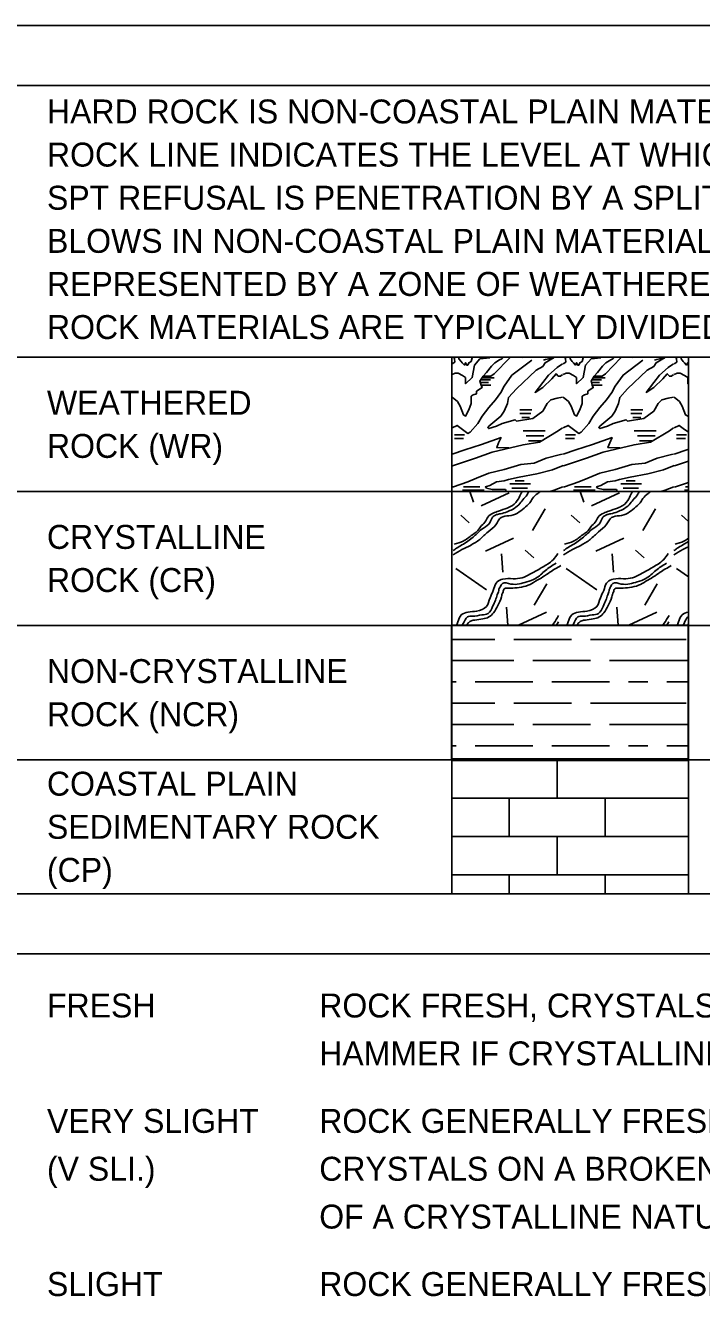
# Model space of a CAD drawing. Extents: x 278618 to 280654, y 171155 to 171855.
# Drawn here: x 280549.54 to 280561.79, y 171598.61 to 171621.7 of the extents above; entities that cross this region are included whole.
import ezdxf

# ---------------------------------------------------------------- set-up
doc = ezdxf.new("R2010")
doc.units = 0
doc.layers.add('Geotech Sheets and Borders Cell', color=7, linetype='Continuous')

msp = doc.modelspace()

# ---------------------------------------------------------------- linework, layer by layer
at = {"layer": 'Geotech Sheets and Borders Cell'}
for p, q in [((280474.148, 171621.702), (280624.148, 171621.702)), ((280474.148, 171620.618), (280624.148, 171620.618)), ((280588.802, 171615.694), (280549.148, 171615.694)), ((280557.265, 171615.694), (280557.265, 171605.977)), ((280557.846, 171615.686), (280557.849, 171615.694)), ((280558.166, 171615.686), (280558.174, 171615.694)), ((280558.526, 171615.686), (280558.535, 171615.694)), ((280559.858, 171615.686), (280559.861, 171615.694)), ((280560.178, 171615.686), (280560.186, 171615.694)), ((280560.538, 171615.686), (280560.547, 171615.694)), ((280561.551, 171615.694), (280561.551, 171605.977)), ((280557.78, 171615.24), (280557.928, 171615.24)), ((280557.793, 171615.284), (280557.965, 171615.284)), ((280557.818, 171615.322), (280558.032, 171615.322)), ((280559.792, 171615.24), (280559.94, 171615.24)), ((280559.805, 171615.284), (280559.977, 171615.284)), ((280559.83, 171615.322), (280560.044, 171615.322)), ((280557.794, 171615.191), (280557.974, 171615.191)), ((280559.806, 171615.191), (280559.986, 171615.191)), ((280558.494, 171614.741), (280558.714, 171614.741)), ((280558.494, 171614.674), (280558.694, 171614.674)), ((280558.534, 171614.606), (280558.674, 171614.606)), ((280560.506, 171614.741), (280560.726, 171614.741)), ((280560.506, 171614.674), (280560.706, 171614.674)), ((280560.546, 171614.606), (280560.686, 171614.606)), ((280558.554, 171614.359), (280558.954, 171614.359)), ((280560.566, 171614.359), (280560.966, 171614.359)), ((280557.314, 171614.291), (280557.494, 171614.291)), ((280557.314, 171614.224), (280557.474, 171614.224)), ((280558.614, 171614.269), (280558.934, 171614.269)), ((280558.654, 171614.179), (280558.874, 171614.179)), ((280559.326, 171614.291), (280559.506, 171614.291)), ((280559.326, 171614.224), (280559.486, 171614.224)), ((280560.626, 171614.269), (280560.946, 171614.269)), ((280560.666, 171614.179), (280560.886, 171614.179)), ((280561.338, 171614.291), (280561.518, 171614.291)), ((280561.338, 171614.224), (280561.498, 171614.224)), ((280558.314, 171613.4), (280558.689, 171613.4)), ((280558.414, 171613.459), (280558.574, 171613.459)), ((280560.326, 171613.4), (280560.701, 171613.4)), ((280560.426, 171613.459), (280560.586, 171613.459)), ((280588.802, 171613.265), (280549.148, 171613.265)), ((280557.455, 171613.285), (280557.849, 171613.285)), ((280557.474, 171613.346), (280557.774, 171613.346)), ((280558.354, 171613.324), (280558.634, 171613.324)), ((280559.467, 171613.285), (280559.861, 171613.285)), ((280559.486, 171613.346), (280559.786, 171613.346)), ((280560.366, 171613.324), (280560.646, 171613.324)), ((280561.479, 171613.285), (280561.551, 171613.285)), ((280561.498, 171613.346), (280561.551, 171613.346)), ((280561.551, 171612.36), (280561.448, 171612.296)), ((280588.802, 171610.836), (280549.148, 171610.836)), ((280559.196, 171610.9), (280559.161, 171610.84)), ((280561.196, 171610.9), (280561.161, 171610.84)), ((280561.551, 171610.868), (280561.535, 171610.84)), ((280557.261, 171610.584), (280557.347, 171610.584)), ((280557.347, 171610.584), (280558.041, 171610.584)), ((280558.388, 171610.584), (280559.43, 171610.584)), ((280559.777, 171610.584), (280560.818, 171610.584)), ((280560.818, 171610.584), (280561.512, 171610.584)), ((280557.261, 171610.202), (280557.347, 171610.202)), ((280557.347, 171610.202), (280558.388, 171610.202)), ((280558.735, 171610.202), (280559.777, 171610.202)), ((280560.124, 171610.202), (280560.818, 171610.202)), ((280560.818, 171610.202), (280561.546, 171610.202)), ((280557.261, 171609.816), (280557.343, 171609.816)), ((280557.69, 171609.816), (280558.731, 171609.816)), ((280559.078, 171609.816), (280560.119, 171609.816)), ((280560.466, 171609.816), (280560.813, 171609.816)), ((280561.16, 171609.816), (280561.546, 171609.816)), ((280557.261, 171609.43), (280557.347, 171609.43)), ((280557.347, 171609.43), (280558.041, 171609.43)), ((280558.388, 171609.43), (280559.43, 171609.43)), ((280559.777, 171609.43), (280560.818, 171609.43)), ((280560.818, 171609.43), (280561.512, 171609.43)), ((280557.261, 171609.044), (280557.347, 171609.044)), ((280557.347, 171609.044), (280558.388, 171609.044)), ((280558.735, 171609.044), (280559.777, 171609.044)), ((280560.124, 171609.044), (280560.818, 171609.044)), ((280560.818, 171609.044), (280561.546, 171609.044)), ((280557.261, 171608.658), (280557.343, 171608.658)), ((280557.69, 171608.658), (280558.731, 171608.658)), ((280559.078, 171608.658), (280560.119, 171608.658)), ((280560.466, 171608.658), (280560.813, 171608.658)), ((280561.16, 171608.658), (280561.546, 171608.658)), ((280588.802, 171608.406), (280549.148, 171608.406)), ((280559.174, 171607.708), (280559.174, 171608.393)), ((280557.265, 171607.708), (280561.551, 171607.708)), ((280558.306, 171607.014), (280558.306, 171607.708)), ((280560.041, 171607.014), (280560.041, 171607.708)), ((280557.265, 171607.014), (280561.551, 171607.014)), ((280559.174, 171606.32), (280559.174, 171607.014)), ((280557.265, 171606.32), (280561.551, 171606.32)), ((280558.306, 171605.977), (280558.306, 171606.32)), ((280560.041, 171605.977), (280560.041, 171606.32)), ((280588.802, 171605.977), (280549.148, 171605.977)), ((280588.802, 171604.892), (280549.148, 171604.892))]:
    msp.add_line(p, q, dxfattribs=at)
for points in [[(280557.27, 171615.578), (280557.32, 171615.606), (280557.311, 171615.665), (280557.301, 171615.694)], [(280558.314, 171615.686), (280558.034, 171615.394), (280557.974, 171615.349), (280557.834, 171615.349), (280557.774, 171615.259), (280557.794, 171615.191), (280557.814, 171615.146), (280557.714, 171615.079), (280557.714, 171615.034), (280557.714, 171615.034), (280557.654, 171615.011), (280557.614, 171614.989), (280557.614, 171614.854), (280557.574, 171614.741), (280557.514, 171614.629), (280557.474, 171614.651), (280557.414, 171614.809), (280557.368, 171614.894)], [(280557.434, 171615.619), (280557.394, 171615.664), (280557.394, 171615.694)], [(280557.434, 171615.619), (280557.454, 171615.596), (280557.494, 171615.551), (280557.514, 171615.596), (280557.534, 171615.551), (280557.554, 171615.551), (280557.574, 171615.596), (280557.614, 171615.619), (280557.634, 171615.686)], [(280557.457, 171615.366), (280557.514, 171615.326), (280557.514, 171615.214), (280557.634, 171615.326), (280557.674, 171615.551), (280557.774, 171615.664), (280557.954, 171615.686)], [(280558.198, 171615.694), (280558.169, 171615.667), (280558.131, 171615.648), (280558.041, 171615.591), (280557.982, 171615.53), (280557.891, 171615.42), (280557.834, 171615.349)], [(280558.794, 171615.461), (280558.914, 171615.529), (280558.954, 171615.596), (280559.074, 171615.664), (280559.114, 171615.686)], [(280558.926, 171615.641), (280558.964, 171615.656), (280559.02, 171615.668), (280559.089, 171615.69), (280559.093, 171615.694)], [(280559.282, 171615.578), (280559.332, 171615.606), (280559.323, 171615.665), (280559.313, 171615.694)], [(280559.326, 171615.686), (280559.34, 171615.694)], [(280560.326, 171615.686), (280560.046, 171615.394), (280559.986, 171615.349), (280559.846, 171615.349), (280559.786, 171615.259), (280559.806, 171615.191), (280559.826, 171615.146), (280559.726, 171615.079), (280559.726, 171615.034), (280559.726, 171615.034), (280559.666, 171615.011), (280559.626, 171614.989), (280559.626, 171614.854), (280559.586, 171614.741), (280559.526, 171614.629), (280559.486, 171614.651), (280559.426, 171614.809), (280559.38, 171614.894)], [(280559.446, 171615.619), (280559.406, 171615.664), (280559.406, 171615.694)], [(280559.446, 171615.619), (280559.466, 171615.596), (280559.506, 171615.551), (280559.526, 171615.596), (280559.546, 171615.551), (280559.566, 171615.551), (280559.586, 171615.596), (280559.626, 171615.619), (280559.646, 171615.686)], [(280559.469, 171615.366), (280559.526, 171615.326), (280559.526, 171615.214), (280559.646, 171615.326), (280559.686, 171615.551), (280559.786, 171615.664), (280559.966, 171615.686)], [(280560.21, 171615.694), (280560.181, 171615.667), (280560.143, 171615.648), (280560.053, 171615.591), (280559.994, 171615.53), (280559.903, 171615.42), (280559.846, 171615.349)], [(280560.806, 171615.461), (280560.926, 171615.529), (280560.966, 171615.596), (280561.086, 171615.664), (280561.126, 171615.686)], [(280560.938, 171615.641), (280560.976, 171615.656), (280561.032, 171615.668), (280561.101, 171615.69), (280561.105, 171615.694)], [(280561.294, 171615.578), (280561.344, 171615.606), (280561.335, 171615.665), (280561.325, 171615.694)], [(280561.338, 171615.686), (280561.352, 171615.694)], [(280561.458, 171615.619), (280561.418, 171615.664), (280561.418, 171615.694)], [(280558.714, 171615.641), (280558.354, 171615.371), (280558.214, 171615.169), (280558.154, 171615.056), (280558.054, 171614.921), (280557.934, 171614.786), (280557.814, 171614.629), (280557.734, 171614.494), (280557.594, 171614.336), (280557.554, 171614.314), (280557.434, 171614.404)], [(280558.794, 171615.461), (280558.434, 171615.124), (280558.294, 171614.966), (280558.274, 171614.854), (280558.214, 171614.719), (280558.154, 171614.629), (280557.934, 171614.449), (280557.914, 171614.426), (280557.934, 171614.404), (280558.074, 171614.449), (280558.174, 171614.494), (280558.414, 171614.561), (280558.434, 171614.539), (280558.734, 171614.584), (280558.914, 171614.719), (280558.992, 171614.859)], [(280559.27, 171615.578), (280559.174, 171615.506), (280559.014, 171615.371), (280558.914, 171615.236), (280558.774, 171615.056), (280558.914, 171615.146), (280559.074, 171615.304), (280559.154, 171615.394), (280559.194, 171615.349), (280559.234, 171615.349), (280559.27, 171615.381)], [(280560.726, 171615.641), (280560.366, 171615.371), (280560.226, 171615.169), (280560.166, 171615.056), (280560.066, 171614.921), (280559.946, 171614.786), (280559.826, 171614.629), (280559.746, 171614.494), (280559.606, 171614.336), (280559.566, 171614.314), (280559.446, 171614.404)], [(280560.806, 171615.461), (280560.446, 171615.124), (280560.306, 171614.966), (280560.286, 171614.854), (280560.226, 171614.719), (280560.166, 171614.629), (280559.946, 171614.449), (280559.926, 171614.426), (280559.946, 171614.404), (280560.086, 171614.449), (280560.186, 171614.494), (280560.426, 171614.561), (280560.446, 171614.539), (280560.746, 171614.584), (280560.926, 171614.719), (280561.004, 171614.859)], [(280561.282, 171615.578), (280561.186, 171615.506), (280561.026, 171615.371), (280560.926, 171615.236), (280560.786, 171615.056), (280560.926, 171615.146), (280561.086, 171615.304), (280561.166, 171615.394), (280561.206, 171615.349), (280561.246, 171615.349), (280561.282, 171615.381)], [(280561.458, 171615.619), (280561.478, 171615.596), (280561.518, 171615.551), (280561.538, 171615.596), (280561.551, 171615.567)], [(280557.457, 171615.366), (280557.379, 171615.405), (280557.325, 171615.405), (280557.27, 171615.381)], [(280559.469, 171615.366), (280559.391, 171615.405), (280559.337, 171615.405), (280559.282, 171615.381)], [(280561.481, 171615.366), (280561.403, 171615.405), (280561.349, 171615.405), (280561.294, 171615.381)], [(280561.481, 171615.366), (280561.538, 171615.326), (280561.538, 171615.214), (280561.551, 171615.227)], [(280557.368, 171614.894), (280557.269, 171614.974)], [(280558.992, 171614.859), (280559.058, 171614.925), (280559.171, 171614.955), (280559.269, 171614.974)], [(280559.38, 171614.894), (280559.281, 171614.974)], [(280561.004, 171614.859), (280561.07, 171614.925), (280561.183, 171614.955), (280561.281, 171614.974)], [(280561.392, 171614.894), (280561.293, 171614.974)], [(280561.551, 171614.654), (280561.538, 171614.629), (280561.498, 171614.651), (280561.438, 171614.809), (280561.392, 171614.894)], [(280557.434, 171614.404), (280557.36, 171614.46), (280557.27, 171614.414)], [(280557.274, 171613.729), (280557.694, 171613.864), (280557.994, 171613.976), (280558.554, 171614.111), (280558.854, 171614.156), (280559.194, 171614.359), (280559.27, 171614.414)], [(280559.446, 171614.404), (280559.372, 171614.46), (280559.282, 171614.414)], [(280559.286, 171613.729), (280559.706, 171613.864), (280560.006, 171613.976), (280560.566, 171614.111), (280560.866, 171614.156), (280561.206, 171614.359), (280561.282, 171614.414)], [(280561.458, 171614.404), (280561.384, 171614.46), (280561.294, 171614.414)], [(280561.551, 171614.335), (280561.458, 171614.404)], [(280557.27, 171613.94), (280557.497, 171614.019), (280557.8, 171614.117), (280558.157, 171614.24), (280558.113, 171614.142), (280558.079, 171614.058), (280558.299, 171614.054)], [(280559.282, 171613.94), (280559.509, 171614.019), (280559.812, 171614.117), (280560.169, 171614.24), (280560.125, 171614.142), (280560.091, 171614.058), (280560.311, 171614.054)], [(280559.27, 171613.94), (280559.234, 171613.931), (280558.974, 171613.864), (280558.754, 171613.774), (280558.514, 171613.751), (280558.214, 171613.661), (280557.934, 171613.594), (280557.714, 171613.504), (280557.554, 171613.436), (280557.294, 171613.346), (280557.274, 171613.346)], [(280561.282, 171613.94), (280561.246, 171613.931), (280560.986, 171613.864), (280560.766, 171613.774), (280560.526, 171613.751), (280560.226, 171613.661), (280559.946, 171613.594), (280559.726, 171613.504), (280559.566, 171613.436), (280559.306, 171613.346), (280559.286, 171613.346)], [(280561.294, 171613.94), (280561.521, 171614.019), (280561.551, 171614.029)], [(280557.265, 171613.732), (280557.269, 171613.733)], [(280558.292, 171613.481), (280558.483, 171613.522), (280558.802, 171613.581), (280559.086, 171613.654), (280559.281, 171613.733)], [(280560.304, 171613.481), (280560.495, 171613.522), (280560.814, 171613.581), (280561.098, 171613.654), (280561.293, 171613.733)], [(280561.298, 171613.729), (280561.551, 171613.811)], [(280558.292, 171613.481), (280558.214, 171613.459), (280558.074, 171613.436), (280557.954, 171613.369), (280557.874, 171613.346), (280557.894, 171613.324), (280557.994, 171613.301), (280558.174, 171613.301), (280558.234, 171613.301), (280558.25, 171613.265)], [(280560.304, 171613.481), (280560.226, 171613.459), (280560.086, 171613.436), (280559.966, 171613.369), (280559.886, 171613.346), (280559.906, 171613.324), (280560.006, 171613.301), (280560.186, 171613.301), (280560.246, 171613.301), (280560.262, 171613.265)], [(280561.551, 171613.427), (280561.318, 171613.346), (280561.298, 171613.346)], [(280557.592, 171613.265), (280557.656, 171613.068)], [(280557.795, 171613.001), (280558.303, 171613.237)], [(280559.041, 171613.265), (280559.12, 171613.287), (280559.274, 171613.346)], [(280559.592, 171613.265), (280559.656, 171613.068)], [(280559.795, 171613.001), (280560.303, 171613.237)], [(280561.053, 171613.265), (280561.132, 171613.287), (280561.286, 171613.346)], [(280558.953, 171612.947), (280558.725, 171612.559)], [(280560.953, 171612.947), (280560.725, 171612.559)], [(280557.425, 171612.833), (280557.581, 171612.697)], [(280559.425, 171612.833), (280559.581, 171612.697)], [(280561.425, 171612.833), (280561.551, 171612.722)], [(280557.873, 171612.185), (280558.381, 171612.421)], [(280559.873, 171612.185), (280560.381, 171612.421)], [(280558.167, 171612.133), (280558.191, 171611.801)], [(280558.595, 171612.2), (280558.751, 171612.064)], [(280560.167, 171612.133), (280560.191, 171611.801)], [(280560.595, 171612.2), (280560.751, 171612.064)], [(280557.338, 171611.868), (280557.894, 171611.484)], [(280559.338, 171611.868), (280559.894, 171611.484)], [(280561.338, 171611.868), (280561.551, 171611.72)], [(280558.987, 171611.593), (280558.759, 171611.205)], [(280560.987, 171611.593), (280560.759, 171611.205)], [(280558.254, 171611.17), (280558.277, 171610.84)], [(280558.471, 171610.841), (280558.979, 171611.077)], [(280560.254, 171611.17), (280560.277, 171610.84)], [(280560.471, 171610.841), (280560.979, 171611.077)]]:
    msp.add_lwpolyline(points, dxfattribs=at)
for points in [[(280557.261, 171610.84), (280561.546, 171610.84), (280561.546, 171608.424), (280557.261, 171608.424)], [(280557.265, 171608.393), (280561.551, 171608.393), (280561.551, 171605.977), (280557.265, 171605.977)]]:
    msp.add_lwpolyline(points, close=True, dxfattribs=at)
for points in [[(280557.308, 171612.312), (280557.468, 171612.364), (280557.636, 171612.48), (280557.76, 171612.588), (280557.784, 171612.624), (280557.864, 171612.708), (280557.916, 171612.8), (280558.016, 171612.872), (280558.108, 171612.908), (280558.268, 171612.964), (280558.364, 171613.012), (280558.472, 171613.132), (280558.52, 171613.232), (280558.541, 171613.265)], [(280558.658, 171613.265), (280558.628, 171613.204), (280558.548, 171613.112), (280558.476, 171613.024), (280558.364, 171612.94), (280558.264, 171612.896), (280558.144, 171612.86), (280558.076, 171612.844), (280558, 171612.796), (280557.976, 171612.748), (280557.932, 171612.672), (280557.808, 171612.58), (280557.724, 171612.504), (280557.648, 171612.436), (280557.556, 171612.364), (280557.448, 171612.296)], [(280558.724, 171613.136), (280558.82, 171613.228), (280558.874, 171613.265)], [(280559.308, 171612.312), (280559.468, 171612.364), (280559.636, 171612.48), (280559.76, 171612.588), (280559.784, 171612.624), (280559.864, 171612.708), (280559.916, 171612.8), (280560.016, 171612.872), (280560.108, 171612.908), (280560.268, 171612.964), (280560.364, 171613.012), (280560.472, 171613.132), (280560.52, 171613.232), (280560.541, 171613.265)], [(280560.658, 171613.265), (280560.628, 171613.204), (280560.548, 171613.112), (280560.476, 171613.024), (280560.364, 171612.94), (280560.264, 171612.896), (280560.144, 171612.86), (280560.076, 171612.844), (280560, 171612.796), (280559.976, 171612.748), (280559.932, 171612.672), (280559.808, 171612.58), (280559.724, 171612.504), (280559.648, 171612.436), (280559.556, 171612.364), (280559.448, 171612.296)], [(280560.724, 171613.136), (280560.82, 171613.228), (280560.874, 171613.265)], [(280557.604, 171612.288), (280557.772, 171612.396), (280557.92, 171612.532), (280558.06, 171612.66), (280558.16, 171612.792), (280558.3, 171612.824), (280558.452, 171612.872), (280558.572, 171612.964), (280558.676, 171613.06), (280558.724, 171613.136)], [(280559.604, 171612.288), (280559.772, 171612.396), (280559.92, 171612.532), (280560.06, 171612.66), (280560.16, 171612.792), (280560.3, 171612.824), (280560.452, 171612.872), (280560.572, 171612.964), (280560.676, 171613.06), (280560.724, 171613.136)], [(280557.448, 171612.296), (280557.348, 171612.236), (280557.288, 171612.192)], [(280557.604, 171612.288), (280557.448, 171612.212), (280557.288, 171612.116)], [(280559.448, 171612.296), (280559.348, 171612.236), (280559.288, 171612.192)], [(280559.604, 171612.288), (280559.448, 171612.212), (280559.288, 171612.116)], [(280561.448, 171612.296), (280561.348, 171612.236), (280561.288, 171612.192)], [(280561.551, 171612.264), (280561.448, 171612.212), (280561.288, 171612.116)], [(280561.308, 171612.312), (280561.468, 171612.364), (280561.551, 171612.417)], [(280559, 171611.948), (280559.1, 171612.028), (280559.184, 171612.14)], [(280561, 171611.948), (280561.1, 171612.028), (280561.184, 171612.14)], [(280558.016, 171611.468), (280558.028, 171611.504), (280558.088, 171611.628), (280558.188, 171611.676), (280558.376, 171611.684), (280558.536, 171611.7), (280558.68, 171611.768), (280558.816, 171611.84), (280559, 171611.948)], [(280558.116, 171611.468), (280558.116, 171611.48), (280558.14, 171611.536), (280558.184, 171611.6), (280558.332, 171611.588), (280558.488, 171611.592), (280558.624, 171611.628), (280558.78, 171611.688), (280558.96, 171611.832), (280559.152, 171611.964)], [(280559.239, 171611.921), (280559.039, 171611.801), (280558.915, 171611.717), (280558.779, 171611.637), (280558.647, 171611.565), (280558.483, 171611.525), (280558.335, 171611.513), (280558.263, 171611.513), (280558.215, 171611.501), (280558.195, 171611.441)], [(280560.016, 171611.468), (280560.028, 171611.504), (280560.088, 171611.628), (280560.188, 171611.676), (280560.376, 171611.684), (280560.536, 171611.7), (280560.68, 171611.768), (280560.816, 171611.84), (280561, 171611.948)], [(280560.116, 171611.468), (280560.116, 171611.48), (280560.14, 171611.536), (280560.184, 171611.6), (280560.332, 171611.588), (280560.488, 171611.592), (280560.624, 171611.628), (280560.78, 171611.688), (280560.96, 171611.832), (280561.152, 171611.964)], [(280561.239, 171611.921), (280561.039, 171611.801), (280560.915, 171611.717), (280560.779, 171611.637), (280560.647, 171611.565), (280560.483, 171611.525), (280560.335, 171611.513), (280560.263, 171611.513), (280560.215, 171611.501), (280560.195, 171611.441)], [(280557.347, 171610.84), (280557.372, 171610.9), (280557.436, 171611.028), (280557.56, 171611.08), (280557.712, 171611.096), (280557.892, 171611.18), (280557.956, 171611.336), (280558.016, 171611.468)], [(280557.448, 171610.84), (280557.472, 171610.872), (280557.548, 171610.992), (280557.64, 171611.004), (280557.808, 171611.028), (280557.92, 171611.056), (280558.004, 171611.18), (280558.056, 171611.296), (280558.088, 171611.392), (280558.116, 171611.468)], [(280558.196, 171611.443), (280558.192, 171611.439), (280558.164, 171611.355), (280558.096, 171611.199), (280558.02, 171611.067), (280557.936, 171610.991), (280557.824, 171610.955), (280557.684, 171610.935), (280557.62, 171610.923), (280557.564, 171610.887), (280557.535, 171610.84)], [(280559.347, 171610.84), (280559.372, 171610.9), (280559.436, 171611.028), (280559.56, 171611.08), (280559.712, 171611.096), (280559.892, 171611.18), (280559.956, 171611.336), (280560.016, 171611.468)], [(280559.448, 171610.84), (280559.472, 171610.872), (280559.548, 171610.992), (280559.64, 171611.004), (280559.808, 171611.028), (280559.92, 171611.056), (280560.004, 171611.18), (280560.056, 171611.296), (280560.088, 171611.392), (280560.116, 171611.468)], [(280560.196, 171611.443), (280560.192, 171611.439), (280560.164, 171611.355), (280560.096, 171611.199), (280560.02, 171611.067), (280559.936, 171610.991), (280559.824, 171610.955), (280559.684, 171610.935), (280559.62, 171610.923), (280559.564, 171610.887), (280559.535, 171610.84)], [(280561.347, 171610.84), (280561.372, 171610.9), (280561.436, 171611.028), (280561.551, 171611.078)], [(280559.088, 171610.84), (280559.112, 171610.876), (280559.2, 171611.016)], [(280561.088, 171610.84), (280561.112, 171610.876), (280561.2, 171611.016)], [(280561.448, 171610.84), (280561.472, 171610.872), (280561.548, 171610.992), (280561.551, 171610.993)]]:
    msp.add_spline(points, degree=3, dxfattribs=at)

# ---------------------------------------------------------------- texts
for s, height, p in [('HARD ROCK IS NON-COASTAL PLAIN MATERIAL THAT WOULD YIELD SPT REFUSAL IF TESTED.  AN INFERRED', 0.43381, (280549.929, 171619.928)), ('ROCK LINE INDICATES THE LEVEL AT WHICH NON-COASTAL PLAIN MATERIAL WOULD YIELD SPT REFUSAL.  ', 0.43381, (280549.929, 171619.147)), ('SPT REFUSAL IS PENETRATION BY A SPLIT SPOON SAMPLER EQUAL TO OR LESS THAN 0.1 FOOT PER 60', 0.43381, (280549.929, 171618.366)), ('BLOWS IN NON-COASTAL PLAIN MATERIAL, THE TRANSITION BETWEEN SOIL AND ROCK IS OFTEN', 0.43381, (280549.929, 171617.585)), ('REPRESENTED BY A ZONE OF WEATHERED ROCK.', 0.43381, (280549.929, 171616.805)), ('ROCK MATERIALS ARE TYPICALLY DIVIDED AS FOLLOWS:', 0.43381, (280549.929, 171616.024)), ('WEATHERED', 0.4338, (280549.929, 171614.653)), ('ROCK (WR)', 0.4338, (280549.929, 171613.872)), ('CRYSTALLINE', 0.43381, (280549.929, 171612.224)), ('ROCK (CR)', 0.4338, (280549.929, 171611.443)), ('NON-CRYSTALLINE', 0.43381, (280549.929, 171609.794)), ('ROCK (NCR)', 0.4338, (280549.929, 171609.013)), ('COASTAL PLAIN', 0.43381, (280549.929, 171607.755)), ('SEDIMENTARY ROCK', 0.43381, (280549.929, 171606.974)), ('(CP)', 0.4338, (280549.929, 171606.194)), ('FRESH', 0.4338, (280549.929, 171603.738)), ('ROCK FRESH, CRYSTALS BRIGHT, FEW JOINTS MAY SHOW SLIGHT STAINING.  ROCK RINGS UNDER ', 0.43381, (280554.862, 171603.738)), ('HAMMER IF CRYSTALLINE.', 0.43381, (280554.862, 171602.871)), ('VERY SLIGHT ', 0.43381, (280549.929, 171601.649)), ('ROCK GENERALLY FRESH, JOINTS STAINED, SOME JOINTS MAY SHOW THIN CLAY COATINGS IF OPEN, ', 0.43381, (280554.862, 171601.649)), ('(V SLI.)', 0.4338, (280549.929, 171600.782)), ('CRYSTALS ON A BROKEN SPECIMEN FACE SHINE BRIGHTLY.  ROCK RINGS UNDER HAMMER BLOWS IF ', 0.43381, (280554.862, 171600.782)), ('OF A CRYSTALLINE NATURE.', 0.43381, (280554.862, 171599.916)), ('SLIGHT', 0.4338, (280549.929, 171598.694)), ('ROCK GENERALLY FRESH, JOINTS STAINED AND DISCOLORATION EXTENDS INTO ROCK UP TO ', 0.43381, (280554.862, 171598.694))]:
    msp.add_text(s, height=height, dxfattribs=at).set_placement(p)

doc.saveas('drawing.dxf')
